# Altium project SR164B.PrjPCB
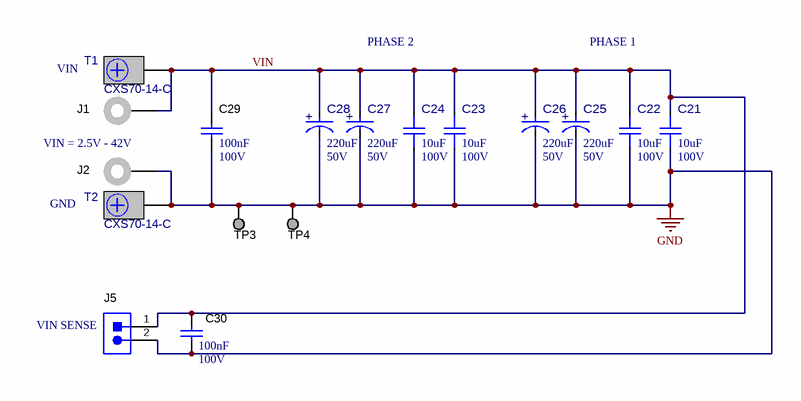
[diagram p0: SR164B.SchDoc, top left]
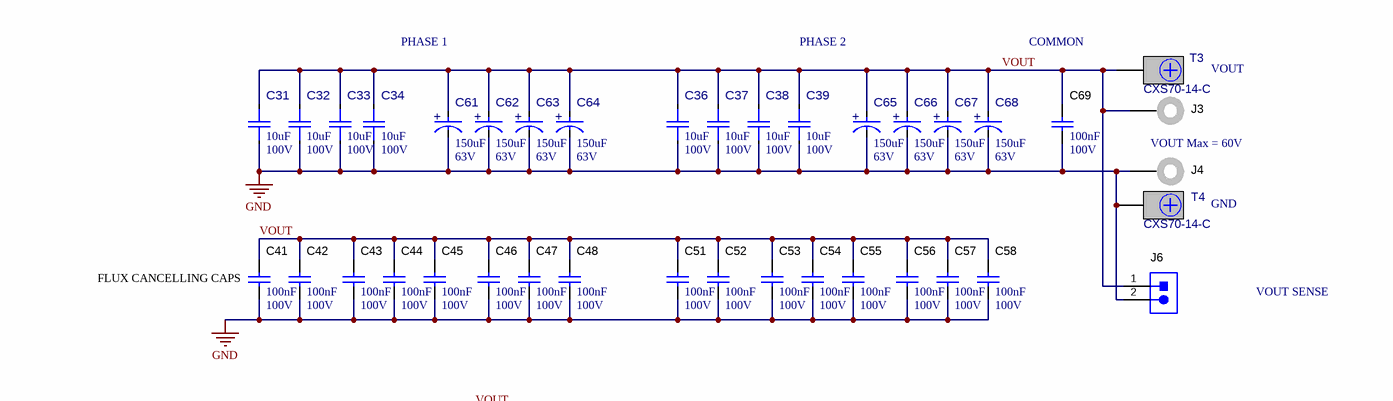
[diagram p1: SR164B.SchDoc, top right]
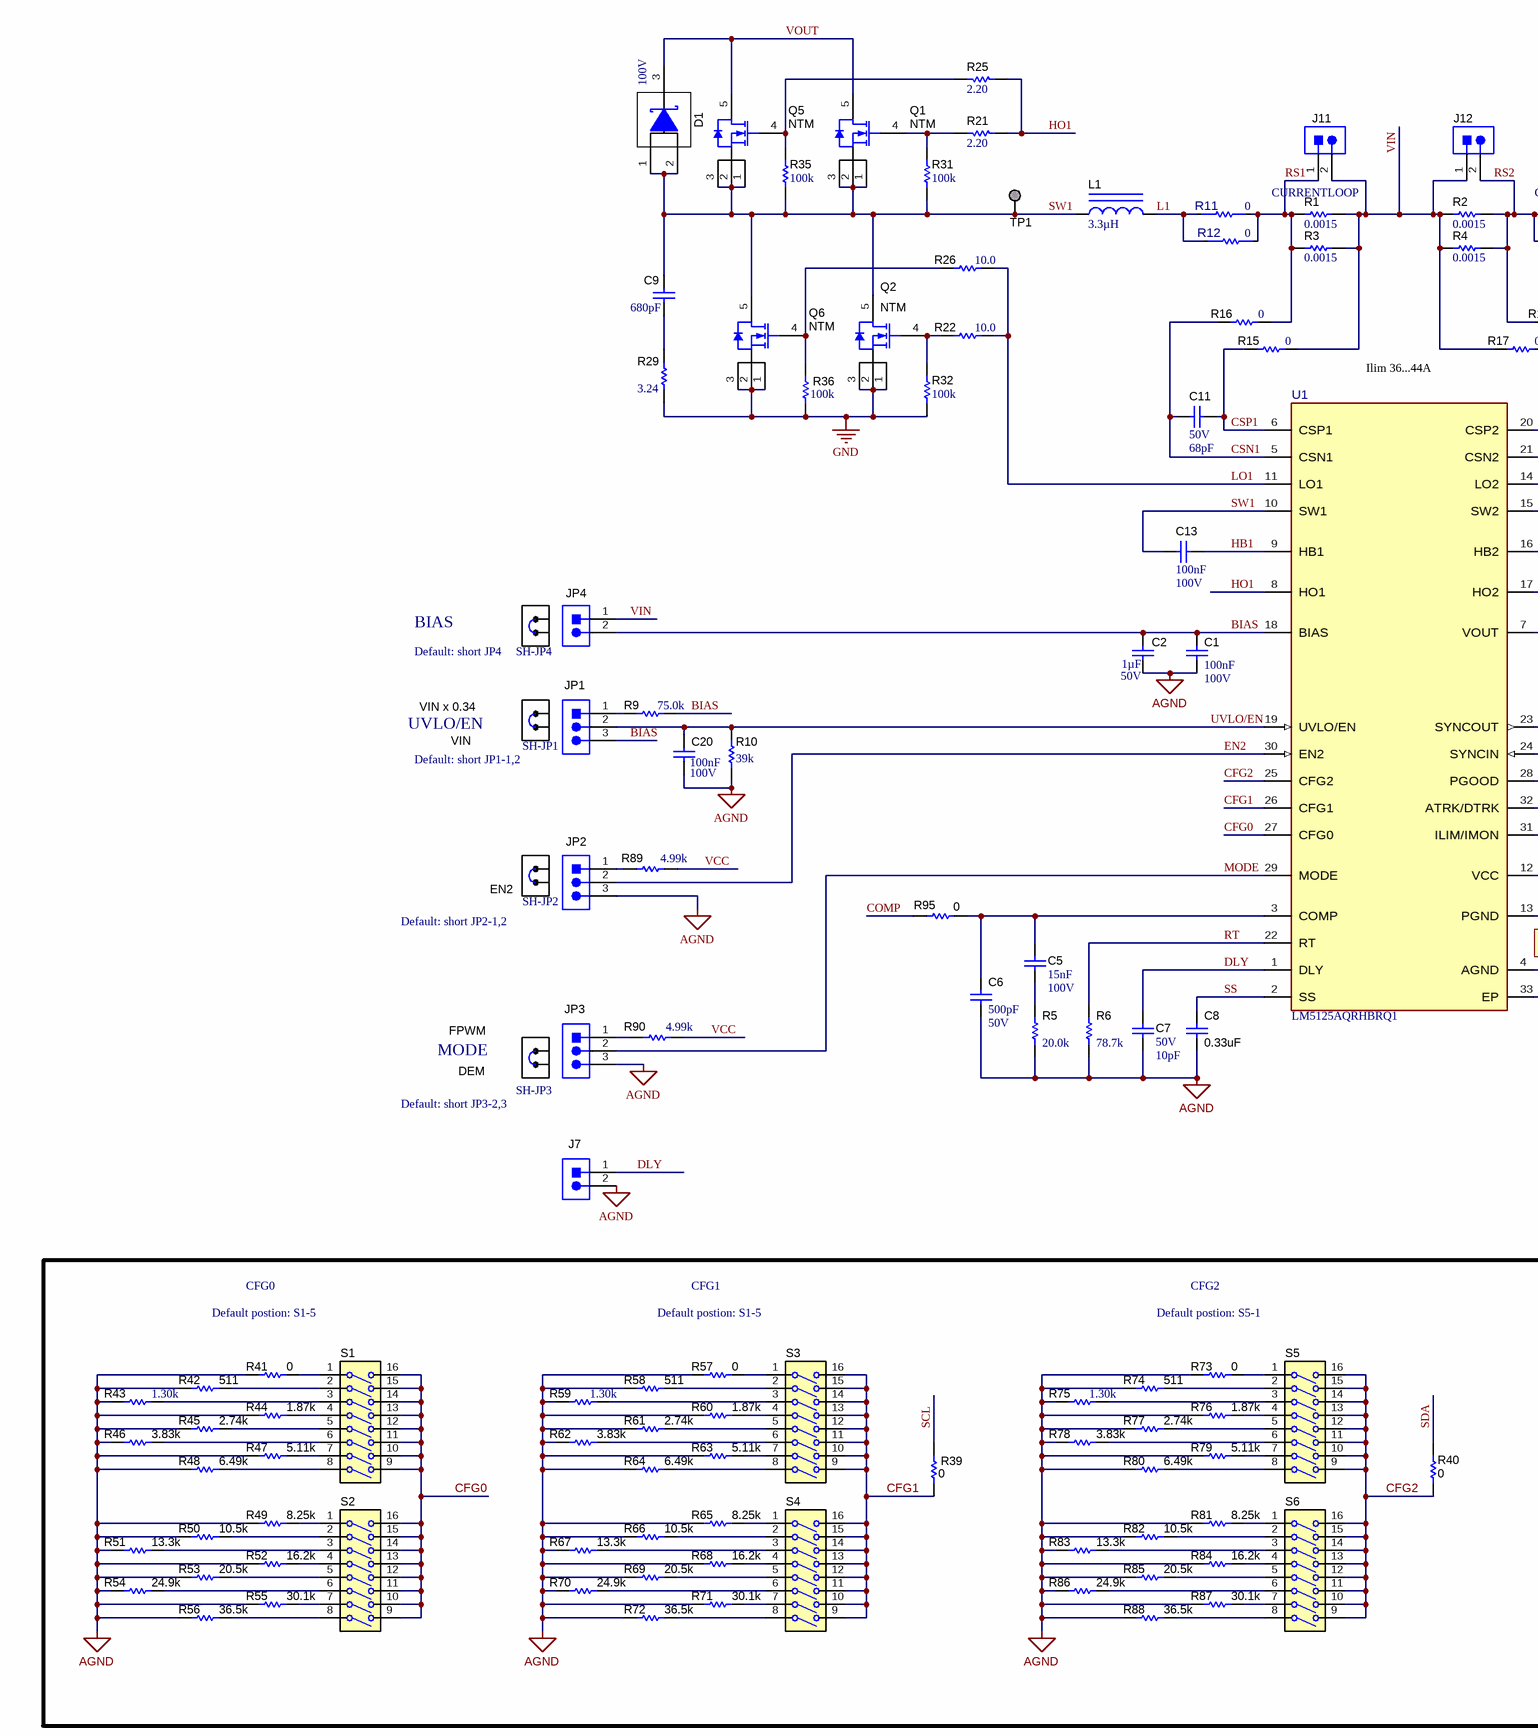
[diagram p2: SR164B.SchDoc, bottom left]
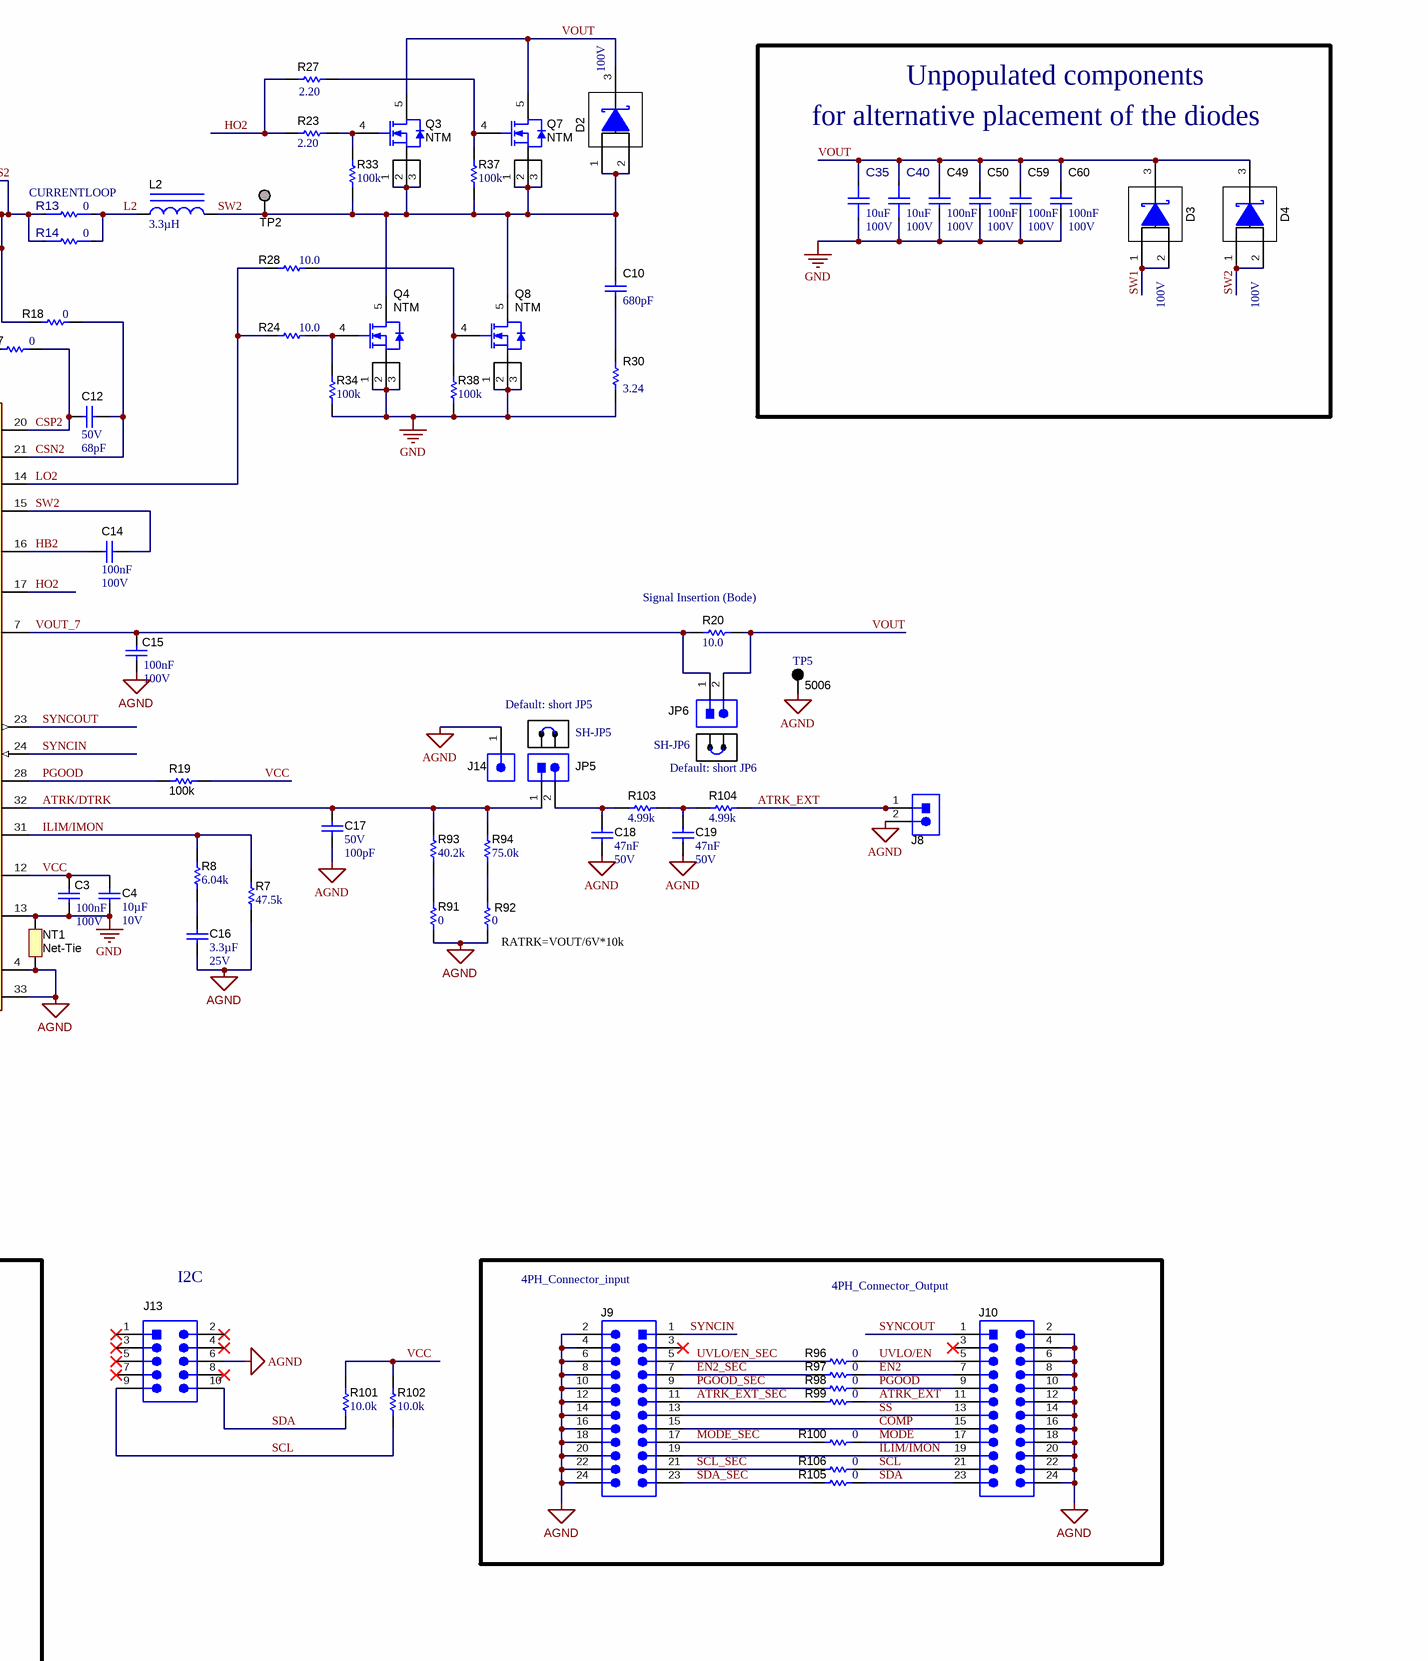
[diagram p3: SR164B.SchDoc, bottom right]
TID: N/A; SCH_Rev: B; PRJ_Title: LM5125AEVM-BST; PRJ_Number: SR164; PRJ_Customer: Public Release; PCB_Rev: A; CopyrightYear: 2025
2 sheets, 255 parts. Net scope: global (net labels, ports and power ports of the same name join across sheets).
Board file: SR164A.PcbDoc
Sheets:
  SR164B.SchDoc
  SR164B_Hardware.SchDoc

## Sheet SR164B.SchDoc: Schematc
size 558 x 431 mm; Date: Not shown in title block; ApprovedBy: Not shown in title block; CheckedBy: Not shown in title block; Author: Not shown in title block; CompanyName: Not shown in title block; Engineer: Not shown in title block; Organization: Not shown in title block; Address1: Not shown in title block; Address2: Not shown in title block; Address3: Not shown in title block; Address4: Not shown in title block; DocumentNumber: 1; Revision: Use project parameter SCH_Rev; SheetNumber: 1; SheetTotal: 2; PageSetup: Record=PageOptions¦CenterHorizontal=True¦CenterVertical=True¦PrintScale=1.00¦XCorrection=1.00¦YCorrection=1.00¦PrintKind=0¦BorderSize=5000000¦LeftOffset=0¦BottomOffset=0¦Orientation=2¦PaperLength=1000¦PaperWidth=1000¦Scale=100¦PaperSource=15¦PrintQuality=600¦MediaType=1¦DitherType=10¦PaperKind=Letter¦PrintScaleMode=1

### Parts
C1  Cap_F: 100nF  VDC_V: 100V  [0603S]  (hidden comment: GRM188R72A104KA35D)
C2  VDC_V: 50V  ValueDisplayed: 1µF  [0805L]  (hidden comment: GCM21BR71H105KA03K)
C3  Cap_F: 100nF  VDC_V: 100V  [0603S]  (hidden comment: GRM188R72A104KA35D)
C4  Cap_F: 10µF  VDC_V: 10V  [0805L]  (hidden comment: GCJ21BR71A106KE01L)
C5  Cap_F: 15nF  VDC_V: 100V  [0603S]  (hidden comment: GCM188R72A153KA37D)
C6  VDC_V: 50V  ValueDisplayed: 500pF  [0603S]  (hidden comment: CC0603JRNPO9BN501)
C7  VDC_V: 50V  ValueDisplayed: 10pF  [0603S]  (hidden comment: C1608C0G1H100D080AA)
C8  ValueDisplayed: 0.33uF  [0603S]  (hidden comment: C0603C334K8PACTU)
C9  value 680pF  [0603S]  (hidden comment: C0603C681K5RACTU)
C10  value 680pF  [0603S]  (hidden comment: C0603C681K5RACTU)
C11  VDC_V: 50V  ValueDisplayed: 68pF  [0402S]  (hidden comment: 04025A680FAT2A)
C12  VDC_V: 50V  ValueDisplayed: 68pF  [0402S]  (hidden comment: 04025A680FAT2A)
C13  Cap_F: 100nF  VDC_V: 100V  [0603S]  (hidden comment: GRM188R72A104KA35D)
C14  Cap_F: 100nF  VDC_V: 100V  [0603S]  (hidden comment: GRM188R72A104KA35D)
C15  Cap_F: 100nF  VDC_V: 100V  [0603S]  (hidden comment: GRM188R72A104KA35D)
C16  Cap_F: 3.3µF  VDC_V: 25V  [0805L]  (hidden comment: C2012X7R1E335K125AB)
C17  VDC_V: 50V  ValueDisplayed: 100pF  [0603S]  (hidden comment: C1608C0G1H101J080AE)
C18  Cap_F: 47nF  VDC_V: 50V  [0603S]  (hidden comment: C1608X7R1H473K080AA)
C19  Cap_F: 47nF  VDC_V: 50V  [0603S]  (hidden comment: C1608X7R1H473K080AA)
C20  Cap_F: 100nF  VDC_V: 100V  [0805L]  (hidden comment: CGA4J2X7R2A104K125AA)
C21  ValueDisplayed: 10uF  VDC_V: 100V  [FP-GRM32EC72A106KE05L_1210-MFG]  (hidden comment: GRM32EC72A106KE05L)
C22  ValueDisplayed: 10uF  VDC_V: 100V  [FP-GRM32EC72A106KE05L_1210-MFG]  (hidden comment: GRM32EC72A106KE05L)
C23  ValueDisplayed: 10uF  VDC_V: 100V  [FP-GRM32EC72A106KE05L_1210-MFG]  (hidden comment: GRM32EC72A106KE05L)
C24  ValueDisplayed: 10uF  VDC_V: 100V  [FP-GRM32EC72A106KE05L_1210-MFG]  (hidden comment: GRM32EC72A106KE05L)
C25  ValueDisplayed: 220uF  VDC_V: 50V  [FP-EEHZU1H221P_RADIAL_SMT-MFG]  (hidden comment: EEHZU1H221P)
C26  ValueDisplayed: 220uF  VDC_V: 50V  [FP-EEHZU1H221P_RADIAL_SMT-MFG]  (hidden comment: EEHZU1H221P)
C27  ValueDisplayed: 220uF  VDC_V: 50V  [FP-EEHZU1H221P_RADIAL_SMT-MFG]  (hidden comment: EEHZU1H221P)
C28  ValueDisplayed: 220uF  VDC_V: 50V  [FP-EEHZU1H221P_RADIAL_SMT-MFG]  (hidden comment: EEHZU1H221P)
C29  Cap_F: 100nF  VDC_V: 100V  [0603S]  (hidden comment: GRM188R72A104KA35D)
C30  Cap_F: 100nF  VDC_V: 100V  [0603S]  (hidden comment: GRM188R72A104KA35D)
C31  ValueDisplayed: 10uF  VDC_V: 100V  [FP-GRM32EC72A106KE05L_1210-MFG]  (hidden comment: GRM32EC72A106KE05L)
C32  ValueDisplayed: 10uF  VDC_V: 100V  [FP-GRM32EC72A106KE05L_1210-MFG]  (hidden comment: GRM32EC72A106KE05L)
C33  ValueDisplayed: 10uF  VDC_V: 100V  [FP-GRM32EC72A106KE05L_1210-MFG]  (hidden comment: GRM32EC72A106KE05L)
C34  ValueDisplayed: 10uF  VDC_V: 100V  [FP-GRM32EC72A106KE05L_1210-MFG]  (hidden comment: GRM32EC72A106KE05L)
C35  ValueDisplayed: 10uF  VDC_V: 100V  [FP-GRM32EC72A106KE05L_1210-MFG]  (hidden comment: GRM32EC72A106KE05L)
C36  ValueDisplayed: 10uF  VDC_V: 100V  [FP-GRM32EC72A106KE05L_1210-MFG]  (hidden comment: GRM32EC72A106KE05L)
C37  ValueDisplayed: 10uF  VDC_V: 100V  [FP-GRM32EC72A106KE05L_1210-MFG]  (hidden comment: GRM32EC72A106KE05L)
C38  ValueDisplayed: 10uF  VDC_V: 100V  [FP-GRM32EC72A106KE05L_1210-MFG]  (hidden comment: GRM32EC72A106KE05L)
C39  ValueDisplayed: 10uF  VDC_V: 100V  [FP-GRM32EC72A106KE05L_1210-MFG]  (hidden comment: GRM32EC72A106KE05L)
C40  ValueDisplayed: 10uF  VDC_V: 100V  [FP-GRM32EC72A106KE05L_1210-MFG]  (hidden comment: GRM32EC72A106KE05L)
C41  Cap_F: 100nF  VDC_V: 100V  [0603S]  (hidden comment: GRM188R72A104KA35D)
C42  Cap_F: 100nF  VDC_V: 100V  [0603S]  (hidden comment: GRM188R72A104KA35D)
C43  Cap_F: 100nF  VDC_V: 100V  [0603S]  (hidden comment: GRM188R72A104KA35D)
C44  Cap_F: 100nF  VDC_V: 100V  [0603S]  (hidden comment: GRM188R72A104KA35D)
C45  Cap_F: 100nF  VDC_V: 100V  [0603S]  (hidden comment: GRM188R72A104KA35D)
C46  Cap_F: 100nF  VDC_V: 100V  [0603S]  (hidden comment: GRM188R72A104KA35D)
C47  Cap_F: 100nF  VDC_V: 100V  [0603S]  (hidden comment: GRM188R72A104KA35D)
C48  Cap_F: 100nF  VDC_V: 100V  [0603S]  (hidden comment: GRM188R72A104KA35D)
C49  Cap_F: 100nF  VDC_V: 100V  [0603S]  (hidden comment: GRM188R72A104KA35D)
C50  Cap_F: 100nF  VDC_V: 100V  [0603S]  (hidden comment: GRM188R72A104KA35D)
C51  Cap_F: 100nF  VDC_V: 100V  [0603S]  (hidden comment: GRM188R72A104KA35D)
C52  Cap_F: 100nF  VDC_V: 100V  [0603S]  (hidden comment: GRM188R72A104KA35D)
C53  Cap_F: 100nF  VDC_V: 100V  [0603S]  (hidden comment: GRM188R72A104KA35D)
C54  Cap_F: 100nF  VDC_V: 100V  [0603S]  (hidden comment: GRM188R72A104KA35D)
C55  Cap_F: 100nF  VDC_V: 100V  [0603S]  (hidden comment: GRM188R72A104KA35D)
C56  Cap_F: 100nF  VDC_V: 100V  [0603S]  (hidden comment: GRM188R72A104KA35D)
C57  Cap_F: 100nF  VDC_V: 100V  [0603S]  (hidden comment: GRM188R72A104KA35D)
C58  Cap_F: 100nF  VDC_V: 100V  [0603S]  (hidden comment: GRM188R72A104KA35D)
C59  Cap_F: 100nF  VDC_V: 100V  [0603S]  (hidden comment: GRM188R72A104KA35D)
C60  Cap_F: 100nF  VDC_V: 100V  [0603S]  (hidden comment: GRM188R72A104KA35D)
C61  ValueDisplayed: 150uF  VDC_V: 63V  [FP-EEHZU1J151P_RADIAL_SMT-MFG]  (hidden comment: EEHZU1J151P)
C62  ValueDisplayed: 150uF  VDC_V: 63V  [FP-EEHZU1J151P_RADIAL_SMT-MFG]  (hidden comment: EEHZU1J151P)
C63  ValueDisplayed: 150uF  VDC_V: 63V  [FP-EEHZU1J151P_RADIAL_SMT-MFG]  (hidden comment: EEHZU1J151P)
C64  ValueDisplayed: 150uF  VDC_V: 63V  [FP-EEHZU1J151P_RADIAL_SMT-MFG]  (hidden comment: EEHZU1J151P)
C65  ValueDisplayed: 150uF  VDC_V: 63V  [FP-EEHZU1J151P_RADIAL_SMT-MFG]  (hidden comment: EEHZU1J151P)
C66  ValueDisplayed: 150uF  VDC_V: 63V  [FP-EEHZU1J151P_RADIAL_SMT-MFG]  (hidden comment: EEHZU1J151P)
C67  ValueDisplayed: 150uF  VDC_V: 63V  [FP-EEHZU1J151P_RADIAL_SMT-MFG]  (hidden comment: EEHZU1J151P)
C68  ValueDisplayed: 150uF  VDC_V: 63V  [FP-EEHZU1J151P_RADIAL_SMT-MFG]  (hidden comment: EEHZU1J151P)
C69  Cap_F: 100nF  VDC_V: 100V  [0603S]  (hidden comment: GRM188R72A104KA35D)
D1  value 100V  [TO-277A]  (hidden comment: V12P10-M3/86A)
D2  value 100V  [TO-277A]  (hidden comment: V12P10-M3/86A)
D3  value 100V  [TO-277A]  (hidden comment: V12P10-M3/86A)
D4  value 100V  [TO-277A]  (hidden comment: V12P10-M3/86A)
J1  108-0740-001  [Johnson_108-0740-001]  (value not drawn)
J2  108-0740-001  [Johnson_108-0740-001]  (value not drawn)
J3  108-0740-001  [Johnson_108-0740-001]  (value not drawn)
J4  108-0740-001  [Johnson_108-0740-001]  (value not drawn)
J5  61300211121  [WURTH_61300211121]  (value not drawn)
J6  61300211121  [WURTH_61300211121]  (value not drawn)
J7  61300211121  [WURTH_61300211121]  (value not drawn)
J8  61300211121  [WURTH_61300211121]  (value not drawn)
J9  TSW-112-07-G-D  [TSW-112-07-G-D]  (value not drawn)
J10  TSW-112-07-G-D  [TSW-112-07-G-D]  (value not drawn)
J11  61300211121  [WURTH_61300211121]  (value not drawn)
J12  61300211121  [WURTH_61300211121]  (value not drawn)
J13  Header_5x2  [CONN_2510-6002]  (value not drawn)
J14  61300111121  [WURTH_61300111121]  (value not drawn)
JP1  61300311121  [WURTH_61300311121]  (value not drawn)
JP2  61300311121  [WURTH_61300311121]  (value not drawn)
JP3  61300311121  [WURTH_61300311121]  (value not drawn)
JP4  61300211121  [WURTH_61300211121]  (value not drawn)
JP5  61300211121  [WURTH_61300211121]  (value not drawn)
JP6  61300211121  [WURTH_61300211121]  (value not drawn)
L1  ValueDisplayed: 3.3µH  [IHLP-6767GZ]  (hidden comment: IHLP6767GZER3R3M5A)
L2  ValueDisplayed: 3.3µH  [IHLP-6767GZ]  (hidden comment: IHLP6767GZER3R3M5A)
NT1  Net-Tie  [Net-Tie_10milWide_30milLong]  (net tie, no BOM)
Q1  NTM  [SO-8FL]
Q2  NTM  [SO-8FL]
Q3  NTM  [SO-8FL]
Q4  NTM  [SO-8FL]
Q5  NTM  [SO-8FL]
Q6  NTM  [SO-8FL]
Q7  NTM  [SO-8FL]
Q8  NTM  [SO-8FL]
R1  ValueDisplayed: 0.0015  [2512_WIDE]  (hidden comment: PML100HZPJV1L5)
R2  ValueDisplayed: 0.0015  [2512_WIDE]  (hidden comment: PML100HZPJV1L5)
R3  ValueDisplayed: 0.0015  [2512_WIDE]  (hidden comment: PML100HZPJV1L5)
R4  ValueDisplayed: 0.0015  [2512_WIDE]  (hidden comment: PML100HZPJV1L5)
R5  ValueDisplayed: 20.0k  [0603S]  (hidden comment: CRCW060320K0FKEA)
R6  ValueDisplayed: 78.7k  [0603S]  (hidden comment: RT0603BRD0778K7L)
R7  ValueDisplayed: 47.5k  [0603S]  (hidden comment: RT0603BRD0747K5L)
R8  ValueDisplayed: 6.04k  [0603S]  (hidden comment: CRCW06036K04FKEA)
R9  ValueDisplayed: 75.0k  [0805L]  (hidden comment: CRCW080575K0FKEA)
R10  ValueDisplayed: 39k  [0805L]  (hidden comment: CRCW080539K0JNEA)
R11  value 0  [FP-WSL080500000ZEA9_0805-MFG]  (hidden comment: WSL080500000ZEA9)
R12  value 0  [FP-WSL080500000ZEA9_0805-MFG]  (hidden comment: WSL080500000ZEA9)
R13  value 0  [FP-WSL080500000ZEA9_0805-MFG]  (hidden comment: WSL080500000ZEA9)
R14  value 0  [FP-WSL080500000ZEA9_0805-MFG]  (hidden comment: WSL080500000ZEA9)
R15  ValueDisplayed: 0  [0603S]  (hidden comment: RMCF0603ZT0R00)
R16  ValueDisplayed: 0  [0603S]  (hidden comment: RMCF0603ZT0R00)
R17  ValueDisplayed: 0  [0603S]  (hidden comment: RMCF0603ZT0R00)
R18  ValueDisplayed: 0  [0603S]  (hidden comment: RMCF0603ZT0R00)
R19  ValueDisplayed: 100k  [0603S]  (hidden comment: CRCW0603100KFKEA)
R20  ValueDisplayed: 10.0  [0603S]  (hidden comment: CRCW060310R0FKEA)
R21  ValueDisplayed: 2.20  [0603S]  (hidden comment: ERJ-3RQF2R2V)
R22  ValueDisplayed: 10.0  [0603S]  (hidden comment: CRCW060310R0FKEA)
R23  ValueDisplayed: 2.20  [0603S]  (hidden comment: ERJ-3RQF2R2V)
R24  ValueDisplayed: 10.0  [0603S]  (hidden comment: CRCW060310R0FKEA)
R25  ValueDisplayed: 2.20  [0603S]  (hidden comment: ERJ-3RQF2R2V)
R26  ValueDisplayed: 10.0  [0603S]  (hidden comment: CRCW060310R0FKEA)
R27  ValueDisplayed: 2.20  [0603S]  (hidden comment: ERJ-3RQF2R2V)
R28  ValueDisplayed: 10.0  [0603S]  (hidden comment: CRCW060310R0FKEA)
R29  ValueDisplayed: 3.24  [1206L]  (hidden comment: CRCW12063R24FKEA)
R30  ValueDisplayed: 3.24  [1206L]  (hidden comment: CRCW12063R24FKEA)
R31  ValueDisplayed: 100k  [0402S]  (hidden comment: CRCW0402100KFKED)
R32  ValueDisplayed: 100k  [0402S]  (hidden comment: CRCW0402100KFKED)
R33  ValueDisplayed: 100k  [0402S]  (hidden comment: CRCW0402100KFKED)
R34  ValueDisplayed: 100k  [0402S]  (hidden comment: CRCW0402100KFKED)
R35  ValueDisplayed: 100k  [0402S]  (hidden comment: CRCW0402100KFKED)
R36  ValueDisplayed: 100k  [0402S]  (hidden comment: CRCW0402100KFKED)
R37  ValueDisplayed: 100k  [0402S]  (hidden comment: CRCW0402100KFKED)
R38  ValueDisplayed: 100k  [0402S]  (hidden comment: CRCW0402100KFKED)
R39  ValueDisplayed: 0  [0603S]  (hidden comment: RMCF0603ZT0R00)
R40  ValueDisplayed: 0  [0603S]  (hidden comment: RMCF0603ZT0R00)
R41  ValueDisplayed: 0  [0603S]  (hidden comment: RMCF0603ZT0R00)
R42  ValueDisplayed: 511  [0603S]  (hidden comment: CRCW0603511RFKEA)
R43  ValueDisplayed: 1.30k  [0603S]  (hidden comment: CRCW06031K30FKEA)
R44  ValueDisplayed: 1.87k  [0603S]  (hidden comment: CRCW06031K87FKEA)
R45  ValueDisplayed: 2.74k  [0603S]  (hidden comment: CRCW06032K74FKEA)
R46  ValueDisplayed: 3.83k  [0603S]  (hidden comment: CRCW06033K83FKEA)
R47  ValueDisplayed: 5.11k  [0603S]  (hidden comment: CRCW06035K11FKEA)
R48  ValueDisplayed: 6.49k  [0603S]  (hidden comment: CRCW06036K49FKEA)
R49  ValueDisplayed: 8.25k  [0603S]  (hidden comment: CRCW06038K25FKEA)
R50  ValueDisplayed: 10.5k  [0603S]  (hidden comment: CRCW060310K5FKEA)
R51  ValueDisplayed: 13.3k  [0603S]  (hidden comment: CRCW060313K3FKEA)
R52  ValueDisplayed: 16.2k  [0603S]  (hidden comment: CRCW060316K2FKEA)
R53  ValueDisplayed: 20.5k  [0603S]  (hidden comment: CRCW060320K5FKEA)
R54  ValueDisplayed: 24.9k  [0603S]  (hidden comment: CRCW060324K9FKEA)
R55  ValueDisplayed: 30.1k  [0603S]  (hidden comment: CRCW060330K1FKEA)
R56  ValueDisplayed: 36.5k  [0603S]  (hidden comment: CRCW060336K5FKEA)
R57  ValueDisplayed: 0  [0603S]  (hidden comment: RMCF0603ZT0R00)
R58  ValueDisplayed: 511  [0603S]  (hidden comment: CRCW0603511RFKEA)
R59  ValueDisplayed: 1.30k  [0603S]  (hidden comment: CRCW06031K30FKEA)
R60  ValueDisplayed: 1.87k  [0603S]  (hidden comment: CRCW06031K87FKEA)
R61  ValueDisplayed: 2.74k  [0603S]  (hidden comment: CRCW06032K74FKEA)
R62  ValueDisplayed: 3.83k  [0603S]  (hidden comment: CRCW06033K83FKEA)
R63  ValueDisplayed: 5.11k  [0603S]  (hidden comment: CRCW06035K11FKEA)
R64  ValueDisplayed: 6.49k  [0603S]  (hidden comment: CRCW06036K49FKEA)
R65  ValueDisplayed: 8.25k  [0603S]  (hidden comment: CRCW06038K25FKEA)
R66  ValueDisplayed: 10.5k  [0603S]  (hidden comment: CRCW060310K5FKEA)
R67  ValueDisplayed: 13.3k  [0603S]  (hidden comment: CRCW060313K3FKEA)
R68  ValueDisplayed: 16.2k  [0603S]  (hidden comment: CRCW060316K2FKEA)
R69  ValueDisplayed: 20.5k  [0603S]  (hidden comment: CRCW060320K5FKEA)
R70  ValueDisplayed: 24.9k  [0603S]  (hidden comment: CRCW060324K9FKEA)
R71  ValueDisplayed: 30.1k  [0603S]  (hidden comment: CRCW060330K1FKEA)
R72  ValueDisplayed: 36.5k  [0603S]  (hidden comment: CRCW060336K5FKEA)
R73  ValueDisplayed: 0  [0603S]  (hidden comment: RMCF0603ZT0R00)
R74  ValueDisplayed: 511  [0603S]  (hidden comment: CRCW0603511RFKEA)
R75  ValueDisplayed: 1.30k  [0603S]  (hidden comment: CRCW06031K30FKEA)
R76  ValueDisplayed: 1.87k  [0603S]  (hidden comment: CRCW06031K87FKEA)
R77  ValueDisplayed: 2.74k  [0603S]  (hidden comment: CRCW06032K74FKEA)
R78  ValueDisplayed: 3.83k  [0603S]  (hidden comment: CRCW06033K83FKEA)
R79  ValueDisplayed: 5.11k  [0603S]  (hidden comment: CRCW06035K11FKEA)
R80  ValueDisplayed: 6.49k  [0603S]  (hidden comment: CRCW06036K49FKEA)
R81  ValueDisplayed: 8.25k  [0603S]  (hidden comment: CRCW06038K25FKEA)
R82  ValueDisplayed: 10.5k  [0603S]  (hidden comment: CRCW060310K5FKEA)
R83  ValueDisplayed: 13.3k  [0603S]  (hidden comment: CRCW060313K3FKEA)
R84  ValueDisplayed: 16.2k  [0603S]  (hidden comment: CRCW060316K2FKEA)
R85  ValueDisplayed: 20.5k  [0603S]  (hidden comment: CRCW060320K5FKEA)
R86  ValueDisplayed: 24.9k  [0603S]  (hidden comment: CRCW060324K9FKEA)
R87  ValueDisplayed: 30.1k  [0603S]  (hidden comment: CRCW060330K1FKEA)
R88  ValueDisplayed: 36.5k  [0603S]  (hidden comment: CRCW060336K5FKEA)
R89  ValueDisplayed: 4.99k  [0603S]  (hidden comment: CRCW06034K99FKEA)
R90  ValueDisplayed: 4.99k  [0603S]  (hidden comment: CRCW06034K99FKEA)
R91  ValueDisplayed: 0  [0805L]  (hidden comment: CRCW08050000Z0EA)
R92  ValueDisplayed: 0  [0805L]  (hidden comment: CRCW08050000Z0EA)
R93  ValueDisplayed: 40.2k  [0805L]  (hidden comment: CRCW080540K2FKEA)
R94  ValueDisplayed: 75.0k  [0805L]  (hidden comment: CRCW080575K0FKEA)
R95  ValueDisplayed: 0  [0603S]  (hidden comment: ERJ-3GEY0R00V)
R96  ValueDisplayed: 0  [0805L]  (hidden comment: CRCW08050000Z0EA)
R97  ValueDisplayed: 0  [0805L]  (hidden comment: CRCW08050000Z0EA)
R98  ValueDisplayed: 0  [0805L]  (hidden comment: CRCW08050000Z0EA)
R99  ValueDisplayed: 0  [0805L]  (hidden comment: CRCW08050000Z0EA)
R100  ValueDisplayed: 0  [0805L]  (hidden comment: CRCW08050000Z0EA)
R101  ValueDisplayed: 10.0k  [0805L]  (hidden comment: CRCW080510K0FKEA)
R102  ValueDisplayed: 10.0k  [0805L]  (hidden comment: CRCW080510K0FKEA)
R103  ValueDisplayed: 4.99k  [0603S]  (hidden comment: CRCW06034K99FKEA)
R104  ValueDisplayed: 4.99k  [0603S]  (hidden comment: CRCW06034K99FKEA)
R105  ValueDisplayed: 0  [0805L]  (hidden comment: CRCW08050000Z0EA)
R106  ValueDisplayed: 0  [0805L]  (hidden comment: CRCW08050000Z0EA)
S1  218-8LPST  [SW_218-8LP]  (value not drawn)
S2  218-8LPST  [SW_218-8LP]  (value not drawn)
S3  218-8LPST  [SW_218-8LP]  (value not drawn)
S4  218-8LPST  [SW_218-8LP]  (value not drawn)
S5  218-8LPST  [SW_218-8LP]  (value not drawn)
S6  218-8LPST  [SW_218-8LP]  (value not drawn)
SH-JP1  SPC02SYAN  [SPC02SYAN]  (value not drawn)
SH-JP2  SPC02SYAN  [SPC02SYAN]  (value not drawn)
SH-JP3  SPC02SYAN  [SPC02SYAN]  (value not drawn)
SH-JP4  SPC02SYAN  [SPC02SYAN]  (value not drawn)
SH-JP5  SPC02SYAN  [SPC02SYAN]  (value not drawn)
SH-JP6  SPC02SYAN  [SPC02SYAN]  (value not drawn)
T1  CXS70-14-C  [Panduit_CXS70-14-C]
T2  CXS70-14-C  [Panduit_CXS70-14-C]
T3  CXS70-14-C  [Panduit_CXS70-14-C]
T4  CXS70-14-C  [Panduit_CXS70-14-C]
TP1  RCU-0C  [TE_RCU]  (value not drawn)
TP2  RCU-0C  [TE_RCU]  (value not drawn)
TP3  RCU-0C  [TE_RCU]  (value not drawn)
TP4  RCU-0C  [TE_RCU]  (value not drawn)
TP5  5006  [Keystone5006]
U1  LM5125AQRHBRQ1  [RHB0032U-MFG]

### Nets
AGND: C1.2 C2.1 C6.2 C7.2 C8.2 C15.2 C16.2 C17.2 C18.2 C19.2 C20.2 J7.2 J8.2 J9.2 J9.4 J9.6 J9.8 J9.10 J9.12 J9.14 J9.16 J9.18 J9.20 J9.22 J9.24 J10.2 J10.4 J10.6 J10.8 J10.10 J10.12 J10.14 J10.16 J10.18 J10.20 J10.22 J10.24 J13.6 J14.1 JP2.3 JP3.3 NT1.1 R5.1 R6.1 R7.1 R10.2 R41.2 R42.1 R43.2 R44.1 R45.2 R46.1 R47.1 R48.1 R49.1 R50.1 R51.1 R52.2 R53.1 R54.1 R55.1 R56.2 R57.2 R58.1 R59.2 R60.1 R61.2 R62.1 R63.1 R64.1 R65.1 R66.1 R67.1 R68.2 R69.1 R70.1 R71.1 R72.2 R73.2 R74.1 R75.2 R76.1 R77.2 R78.1 R79.1 R80.1 R81.1 R82.1 R83.1 R84.2 R85.1 R86.1 R87.1 R88.2 R91.1 R92.1 TP5.1 U1.4(AGND) U1.33(EP)
GND: C3.2 C4.2 C21.1 C22.1 C23.1 C24.1 C25.1(CATHODE) C26.1(CATHODE) C27.1(CATHODE) C28.1(CATHODE) C29.2 C30.2 C31.1 C32.1 C33.1 C34.1 C35.1 C36.1 C37.1 C38.1 C39.1 C40.1 C41.2 C42.2 C43.2 C44.2 C45.2 C46.2 C47.2 C48.2 C49.2 C50.2 C51.2 C52.2 C53.2 C54.2 C55.2 C56.2 C57.2 C58.2 C59.2 C60.2 C61.1(CATHODE) C62.1(CATHODE) C63.1(CATHODE) C64.1(CATHODE) C65.1(CATHODE) C66.1(CATHODE) C67.1(CATHODE) C68.1(CATHODE) C69.2 J2.1 J4.1 J5.2 J6.2 NT1.2 Q2.1(S) Q2.2(S) Q2.3(S) Q4.1(S) Q4.2(S) Q4.3(S) Q6.1(S) Q6.2(S) Q6.3(S) Q8.1(S) Q8.2(S) Q8.3(S) R29.1 R30.1 R32.1 R34.1 R36.1 R38.1 T2.1 T4.1 TP3.1 TP4.1 U1.13(PGND)
ATRK/DTRK: C17.1 JP5.1 R93.2 R94.2 U1.32(ATRK/DTRK)
ATRK_EXT: J8.1 J10.11 R99.1 R104.2
ATRK_EXT_SEC: J9.11 R99.2
BIAS: C1.1 C2.2 JP1.3 JP4.2 R9.1 U1.18(BIAS)
CFG0: S1.9(8A) S1.10(7A) S1.11(6A) S1.12(5A) S1.13(4A) S1.14(3A) S1.15(2A) S1.16(1A) S2.9(8A) S2.10(7A) S2.11(6A) S2.12(5A) S2.13(4A) S2.14(3A) S2.15(2A) S2.16(1A) U1.27(CFG0)
CFG1: R39.2 S3.9(8A) S3.10(7A) S3.11(6A) S3.12(5A) S3.13(4A) S3.14(3A) S3.15(2A) S3.16(1A) S4.9(8A) S4.10(7A) S4.11(6A) S4.12(5A) S4.13(4A) S4.14(3A) S4.15(2A) S4.16(1A) U1.26(CFG1)
CFG2: R40.2 S5.9(8A) S5.10(7A) S5.11(6A) S5.12(5A) S5.13(4A) S5.14(3A) S5.15(2A) S5.16(1A) S6.9(8A) S6.10(7A) S6.11(6A) S6.12(5A) S6.13(4A) S6.14(3A) S6.15(2A) S6.16(1A) U1.25(CFG2)
COMP: J9.15 J10.15 R95.1
CSN1: C11.2 R16.1 U1.5(CSN1)
CSN2: C12.1 R18.1 U1.21(CSN2)
CSP1: C11.1 R15.1 U1.6(CSP1)
CSP2: C12.2 R17.1 U1.20(CSP2)
DLY: C7.1 J7.1 U1.1(DLY)
EN2: J10.7 JP2.2 R97.1 U1.30(EN2)
EN2_SEC: J9.7 R97.2
HB1: C13.2 U1.9(HB1)
HB2: C14.1 U1.16(HB2)
HO1: R21.2 R25.2 U1.8(HO1)
HO2: R23.1 R27.1 U1.17(HO2)
ILIM/IMON: J9.19 J10.19 R7.2 R8.2 U1.31(ILIM/IMON)
L1: L1.2 R11.1 R12.1
L2: L2.1 R13.2 R14.2
LO1: R22.1 R26.1 U1.11(LO1)
LO2: R24.2 R28.2 U1.14(LO2)
MODE: J10.17 JP3.2 R100.1 U1.29(MODE)
MODE_SEC: J9.17 R100.2
PGOOD: J10.9 R19.2 R98.1 U1.28(PGOOD)
PGOOD_SEC: J9.9 R98.2
RS1: J11.1 R1.1 R3.1 R11.2 R12.2 R16.2
RS2: J12.2 R2.2 R4.2 R13.1 R14.1 R18.2
RT: R6.2 U1.22(RT)
SCL: J10.21 J13.9 R39.1 R102.1 R106.1
SCL_SEC: J9.21 R106.2
SDA: J10.23 J13.10 R40.1 R101.1 R105.1
SDA_SEC: J9.23 R105.2
SS: C8.1 J9.13 J10.13 U1.2(SS)
SW1: C9.1 C13.1 D1.1(A) D1.2(A) D3.1(A) D3.2(A) L1.1 Q1.1(S) Q1.2(S) Q1.3(S) Q2.5(D) Q5.1(S) Q5.2(S) Q5.3(S) Q6.5(D) R31.1 R35.1 TP1.1 U1.10(SW1)
SW2: C10.1 C14.2 D2.1(A) D2.2(A) D4.1(A) D4.2(A) L2.2 Q3.1(S) Q3.2(S) Q3.3(S) Q4.5(D) Q7.1(S) Q7.2(S) Q7.3(S) Q8.5(D) R33.1 R37.1 TP2.1 U1.15(SW2)
SYNCIN: J9.1 U1.24(SYNCIN)
SYNCOUT: J10.1 U1.23(SYNCOUT)
UVLO/EN: C20.1 J10.5 JP1.2 R10.1 R96.1 U1.19(UVLO/EN)
UVLO/EN_SEC: J9.5 R96.2
VCC: C3.1 C4.1 R19.1 R89.2 R90.2 R101.2 R102.2 U1.12(VCC)
VIN: C21.2 C22.2 C23.2 C24.2 C25.2(ANODE) C26.2(ANODE) C27.2(ANODE) C28.2(ANODE) C29.1 C30.1 J1.1 J5.1 J11.2 J12.1 JP4.1 R1.2 R2.1 R3.2 R4.1 R15.2 R17.2 T1.1
VOUT: C31.2 C32.2 C33.2 C34.2 C35.2 C36.2 C37.2 C38.2 C39.2 C40.2 C41.1 C42.1 C43.1 C44.1 C45.1 C46.1 C47.1 C48.1 C49.1 C50.1 C51.1 C52.1 C53.1 C54.1 C55.1 C56.1 C57.1 C58.1 C59.1 C60.1 C61.2(ANODE) C62.2(ANODE) C63.2(ANODE) C64.2(ANODE) C65.2(ANODE) C66.2(ANODE) C67.2(ANODE) C68.2(ANODE) C69.1 D1.3(K) D2.3(K) D3.3(K) D4.3(K) J3.1 J6.1 JP6.2 Q1.5(D) Q3.5(D) Q5.5(D) Q7.5(D) R20.1 T3.1
VOUT_7: C15.1 JP6.1 R20.2 U1.7(VOUT)
NetC5_1: C5.1 C6.1 R95.2 U1.3(COMP)
NetC5_2: C5.2 R5.2
NetC9_2: C9.2 R29.2
NetC10_2: C10.2 R30.2
NetC16_1: C16.1 R8.1
NetC18_1: C18.1 JP5.2 R103.1
NetC19_1: C19.1 R103.2 R104.1
NetJP1_1: JP1.1 R9.2
NetJP2_1: JP2.1 R89.1
NetJP3_1: JP3.1 R90.1
NetQ1_4: Q1.4(G) R21.1 R31.2
NetQ2_4: Q2.4(G) R22.2 R32.2
NetQ3_4: Q3.4(G) R23.2 R33.2
NetQ4_4: Q4.4(G) R24.1 R34.2
NetQ5_4: Q5.4(G) R25.1 R35.2
NetQ6_4: Q6.4(G) R26.2 R36.2
NetQ7_4: Q7.4(G) R27.2 R37.2
NetQ8_4: Q8.4(G) R28.1 R38.2
NetR41_1: R41.1 S1.1
NetR42_2: R42.2 S1.2
NetR43_1: R43.1 S1.3
NetR44_2: R44.2 S1.4
NetR45_1: R45.1 S1.5
NetR46_2: R46.2 S1.6
NetR47_2: R47.2 S1.7
NetR48_2: R48.2 S1.8
NetR49_2: R49.2 S2.1
NetR50_2: R50.2 S2.2
NetR51_2: R51.2 S2.3
NetR52_1: R52.1 S2.4
NetR53_2: R53.2 S2.5
NetR54_2: R54.2 S2.6
NetR55_2: R55.2 S2.7
NetR56_1: R56.1 S2.8
NetR57_1: R57.1 S3.1
NetR58_2: R58.2 S3.2
NetR59_1: R59.1 S3.3
NetR60_2: R60.2 S3.4
NetR61_1: R61.1 S3.5
NetR62_2: R62.2 S3.6
NetR63_2: R63.2 S3.7
NetR64_2: R64.2 S3.8
NetR65_2: R65.2 S4.1
NetR66_2: R66.2 S4.2
NetR67_2: R67.2 S4.3
NetR68_1: R68.1 S4.4
NetR69_2: R69.2 S4.5
NetR70_2: R70.2 S4.6
NetR71_2: R71.2 S4.7
NetR72_1: R72.1 S4.8
NetR73_1: R73.1 S5.1
NetR74_2: R74.2 S5.2
NetR75_1: R75.1 S5.3
NetR76_2: R76.2 S5.4
NetR77_1: R77.1 S5.5
NetR78_2: R78.2 S5.6
NetR79_2: R79.2 S5.7
NetR80_2: R80.2 S5.8
NetR81_2: R81.2 S6.1
NetR82_2: R82.2 S6.2
NetR83_2: R83.2 S6.3
NetR84_1: R84.1 S6.4
NetR85_2: R85.2 S6.5
NetR86_2: R86.2 S6.6
NetR87_2: R87.2 S6.7
NetR88_1: R88.1 S6.8
NetR91_2: R91.2 R93.1
NetR92_2: R92.2 R94.1

Not connected (* = marked no-connect by the designer): J9 3*; J10 3*; J13 1* 2* 3* 4* 5* 7* 8*

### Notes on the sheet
- VIN
- PHASE 2
- PHASE 1
- COMMON
- VOUT
- VIN = 2.5V - 42V
- VOUT Max = 60V
- GND
- (near C41) FLUX CANCELLING CAPS
- (near J5) VIN SENSE
- (near J6) VOUT SENSE
- Unpopulated components
- for alternative placement of the diodes
- (near R11) CURRENTLOOP
- (near R13) CURRENTLOOP
- Ilim 36...44A
- BIAS
- (near SH-JP4) Default: short JP4
- (near R20) Signal Insertion (Bode)
- UVLO/EN
- VIN x 0.34
- (near SH-JP5) Default: short JP5
- Default: short JP1-1,2
- (near SH-JP6) Default: short JP6
- Default: short JP2-1,2
- (near SH-JP2) EN2
- (near R92) RATRK=VOUT/6V*10k
- MODE
- FPWM
- Default: short JP3-2,3
- DEM
- Default postion: S1-5
- CFG0
- CFG1
- Default postion: S5-1
- CFG2
- (near J13) I2C
- (near J9) 4PH_Connector_input
- 4PH_Connector_Output

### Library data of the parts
C1 C3 C13-C15 C29 C30 C41-C60 C69 = CMP-0007469-4: CAP, CERM, 0.1 uF, 100 V, +/- 10%, X7R, 0603; Manufacturer: MuRata; TaMin_C: -55°C; Polarized: N; SizeAreaWB_mm2: 4.68; Value1: Unknown; U/M: EA; Value: 0.1uF; TaMax_C: 125°C; SizeZ_mm: 1; SizeX_mm: 1.6; SizeY_mm: 0.8; Cap_Case: 0603; SizeArea_mm2: 1.28; AEC Category: Q200
C2 = CMP-0086249-1: CAP, CERM, 1 µF, 50 V,+/- 10%, X7R, AEC-Q200 Grade 1, 0805; Manufacturer: MuRata; TaMin_C: -55°C; Polarized: N; SizeAreaWB_mm2: 6.75; U/M: EA; Value: 1uF; TaMax_C: 125°C; SizeZ_mm: 1.45; SizeX_mm: 2; SizeY_mm: 1.25; Cap_Case: 0805; SizeArea_mm2: 2.5; AEC Qualified: Y; AEC Grade: 1; AEC Category: Q200
C4 = CMP-0079153-1: CAP, CERM, 10 µF, 10 V,+/- 10%, X7R, AEC-Q200 Grade 1, 0805; Manufacturer: MuRata; SizeAreaWB_mm2: 6.75; SizeArea_mm2: 2.5; AEC Qualified: Y; AEC Category: Q200; Value: 10uF; TaMax_C: 125°C; SizeZ_mm: 1.45; AEC Grade: 1; Polarized: N; TaMin_C: -55°C; SizeY_mm: 1.25; U/M: EA; SizeX_mm: 2; Cap_Case: 0805
C5 = CMP-0007147-5: CAP, CERM, 0.015 uF, 100 V, +/- 10%, X7R, AEC-Q200 Grade 1, 0603; Manufacturer: MuRata; TaMin_C: -55°C; Polarized: N; SizeAreaWB_mm2: 4.68; Value1: Unknown; U/M: EA; TaMax_C: 125°C; SizeZ_mm: 1; SizeX_mm: 1.6; SizeY_mm: 0.8; Cap_Case: 0603; SizeArea_mm2: 1.28; AEC Qualified: Y; AEC Category: Q200
C6 = CMP-0007064-4: CAP, CERM, 500 pF, 50 V, +/- 5%, C0G/NP0, 0603; Manufacturer: Yageo America; TaMin_C: -55°C; Polarized: N; SizeAreaWB_mm2: 4.68; Value1: Unknown; U/M: EA; Value: 500pF; TaMax_C: 125°C; SizeZ_mm: 1; SizeX_mm: 1.6; SizeY_mm: 0.8; Cap_Case: 0603; SizeArea_mm2: 1.28; AEC Category: Q200
C7 = CMP-0006988-4: CAP, CERM, 10 pF, 50 V, +/- 5%, C0G/NP0, 0603; Manufacturer: TDK; TaMin_C: -55°C; ESR_ohm: 0.3492; Polarized: N; SizeAreaWB_mm2: 4.68; Value1: 0.3492 ohm; U/M: EA; Value: 10pF; TaMax_C: 125°C; SizeZ_mm: 1; SizeX_mm: 1.6; SizeY_mm: 0.8; Cap_Case: 0603; SizeArea_mm2: 1.28; AEC Category: Q200
C8 = CMP-0006925-5: CAP, CERM, 0.33 uF, 10 V, +/- 10%, X5R, 0603; Manufacturer: Kemet; TaMin_C: -55°C; Polarized: N; SizeAreaWB_mm2: 4.68; Value1: Unknown; U/M: EA; Value: 0.33uF; TaMax_C: 85°C; SizeZ_mm: 1; SizeX_mm: 1.6; SizeY_mm: 0.8; Cap_Case: 0603; Value2: 10V; SizeArea_mm2: 1.28; Cap_F: 330nF; AEC Category: Q200
C9 C10 = CMP-0006960-4: CAP, CERM, 680 pF, 50 V, +/- 10%, X7R, 0603; Manufacturer: Kemet; TaMin_C: -55°C; Polarized: N; SizeAreaWB_mm2: 4.68; Value1: Unknown; U/M: EA; TaMax_C: 125°C; SizeZ_mm: 1; SizeX_mm: 1.6; SizeY_mm: 0.8; Cap_Case: 0603; Value2: 50V; SizeArea_mm2: 1.28; AEC Category: Q200
C11 C12 = CMP-0085815-1: CAP, CERM, 68 pF, 50 V,+/- 1%, C0G/NP0, 0402; Manufacturer: AVX; SizeArea_mm2: 0.5; SizeAreaWB_mm2: 3; Green_REACh: Incomplete; TaMax_C: 125°C; Value: 68pF; Cap_Case: 0402; SizeX_mm: 1; TaMin_C: -55°C; AEC Qualified: N; AEC Category: Q200; SizeZ_mm: 0.6; U/M: EA; Green_Lifecycle: Active
C16 = CMP-0007868-2: CAP, CERM, 3.3 uF, 25 V, +/- 10%, X7R, 0805; Manufacturer: TDK; TaMin_C: -55°C; Polarized: N; SizeAreaWB_mm2: 6.75; Value1: Unknown; U/M: EA; Value: 3.3uF; TaMax_C: 125°C; SizeZ_mm: 1.45; SizeX_mm: 2; SizeY_mm: 1.25; Cap_Case: 0805; SizeArea_mm2: 2.5; AEC Category: Q200
C17 = CMP-0006989-4: CAP, CERM, 100 pF, 50 V, +/- 5%, C0G/NP0, 0603; Manufacturer: TDK; TaMin_C: -55°C; Polarized: N; SizeAreaWB_mm2: 4.68; Value1: Unknown; U/M: EA; Value: 100pF; TaMax_C: 125°C; SizeZ_mm: 1; SizeX_mm: 1.6; SizeY_mm: 0.8; Cap_Case: 0603; SizeArea_mm2: 1.28; AEC Category: Q200
C18 C19 = CMP-0007049-4: CAP, CERM, 0.047 uF, 50 V, +/- 10%, X7R, 0603; Manufacturer: TDK; TaMin_C: -55°C; ESR_ohm: 49.007m; Polarized: N; SizeAreaWB_mm2: 4.68; Value1: 0.049007 ohm; U/M: EA; TaMax_C: 125°C; SizeZ_mm: 1; SizeX_mm: 1.6; SizeY_mm: 0.8; Cap_Case: 0603; SizeArea_mm2: 1.28; IRMS_A: 767.528mA; AEC Category: Q200
C20 = CMP-0007969-2: CAP, CERM, 0.1 uF, 100 V, +/- 10%, X7R, AEC-Q200 Grade 1, 0805; Manufacturer: TDK; TaMin_C: -55°C; ESR_ohm: 20.726m; Polarized: N; SizeAreaWB_mm2: 6.75; Value1: 0.020726 ohm; U/M: EA; Value: 0.1uF; TaMax_C: 125°C; SizeZ_mm: 1.45; SizeX_mm: 2; SizeY_mm: 1.25; Cap_Case: 0805; SizeArea_mm2: 2.5; AEC Qualified: Y; IRMS_A: 1.456A; AEC Grade: 1; AEC Category: Q200
C21-C24 C31-C40 = CMP-0087970-1: 10µF ±10% 100V Ceramic Capacitor X7S 1210 (3225 Metric); Manufacturer: Murata; Symbol Name: SYM-GRM32EC72A106KE05L; AEC Qualified: No; TempCo: 22%; SizeZ_mm: 2.7mm
C25-C28 = CMP-0120360-1: Aluminum Hybrid Polymer Capacitors 220uF 20% 50V Life 4000Hours AEC-Q200 RADIAL SMT; Manufacturer: Panasonic; AEC Grade: Grade 1; AEC Qualified: Yes; Cap_F: 220µF; IRMS_A: 5.2A; SizeZ_mm: 16.8mm; Dissipation Factor: 10%; Esr: 10mΩ; Leakage Current: 110uA; Value: 220µF
C61-C68 = CMP-0120392-1: Aluminum Hybrid Polymer Capacitors 150uF 20% 63V Life 4000Hours AEC-Q200 RADIAL SMT; Manufacturer: Panasonic; AEC Grade: Grade 1; AEC Qualified: Yes; Cap_F: 150µF; IRMS_A: 5.2A; SizeZ_mm: 16.8mm; Dissipation Factor: 8%; Esr: 10mΩ; Leakage Current: 94.5uA; Value: 150µF
D1-D4 = CMP-0028832-2: Diode, Schottky, 100 V, 12 A, AEC-Q101, TO-277A; Manufacturer: Vishay-Semiconductor; SizeArea_mm2: 30.875; Vf_V: 700mV; TJmax_C: 150°C; SizeZ_mm: 1.2; AEC Category: Q101; Value2: 0.7V; Green_Lifecycle: Not Set; SizeY_mm: 4.75; Green_REACh: Incomplete; Value1: 12A; SizeX_mm: 6.5; AEC Qualified: Y; SizeAreaWB_mm2: 57.375
J1-J4 = CMP-0055387-2: Standard Banana Jack, Uninsulated, 15A; Manufacturer: Cinch Connectivity; CNHeader: FALSE; Green_Lifecycle: Active; Green_REACh: Passed; CT: TRUE
J5-J8 J11 J12 JP4-JP6 = CMP-0054794-2: Header, 2.54 mm, 2x1, Gold, TH; Manufacturer: Wurth Elektronik; Shrouded: N; Gender: Male; Green_REACh: Passed; Pitch_mm: 2.54; Green_Lifecycle: Active; Row_Count: 1; Cert_UL: Y
J9 J10 = CMP-0075423-1: Header, 100mil, 12x2, Gold, TH; Manufacturer: Samtec; Pitch_mm: 2.54; Cert_VDE: N; Gender: Male; Cert_CSA: Y; Current_A: 6.3A; Voltage_V: 550V; CT: False; Row_Count: 2; CNHeader: True
J13 = CMP-0055448-2: Header (shrouded), 100mil, 5x2, High-Temperature, Gold, TH; PartNumber: N2510-6002-RB; Manufacturer: 3M; Green_Lifecycle: Active; Green_REACh: Passed
J14 = CMP-0054792-1: Header, 2.54 mm, 1x1, Gold, TH; Manufacturer: Wurth Elektronik; CNHeader: TRUE; CT: FALSE
JP1-JP3 = CMP-0054796-4: Header, 2.54 mm, 3x1, Gold, TH; Manufacturer: Wurth Elektronik; Green_Lifecycle: Active; Green_REACh: Passed; CT: FALSE; CNHeader: TRUE
L1 L2 = CMP-0750174-1: Inductor, Shielded, 3.3 µH, 32.2 A, 0.00327 ohm, AEC-Q200 Grade 0, SMD; Manufacturer: Vishay-Dale; Value: 3.3uH; AEC Grade: 0; SizeAreaWB_mm2: 366.7225; AEC Category: Q200; AEC Qualified: Y; Irms: 32.2A @ 40C rise; SizeX_mm: 17.15; Value2: 32.2A; SizeZ_mm: 7; Isat: 32A @ 20% inductance drop; SizeArea_mm2: 294.1225; DCR_ohm: 3.27m
NT1 = CMP-0078142-6: Single point connection between nets.
Q1-Q8 = CMP-0000853-1: MOSFET, N-CH, 60 V, 71 A, SO-8FL; PartNumber: NTMFS5C670NLT1G; Alternate Manufacturer: None; Manufacturer: ON Semiconductor; Value2: 20 nC; QgTyp_nC: 20; VdsMax_V: 60V; Value1: 0.008; Rdson45_ohm: 8.8m; SizeAreaWB_mm2: 58.2725; AEC Category: Q101; SizeX_mm: 6.15; Vgs_V: 20V; IdsMax_A: 71A; SizeZ_mm: 1.1; SizeY_mm: 5.15; AEC Qualified: N; Value: 60V; SizeArea_mm2: 31.6725; U/M: EA
R1-R4 = CMP-0084409-1: RES, 0.0015, 5%, 2 W, 2512 WIDE; Manufacturer: Rohm; Value_Code: 1L500; Res_ohm: 1.5m; AEC Qualified: N; Value: 0.0015; SizeArea_mm2: 20.16; SizeY_mm: 6.3; SizeAreaWB_mm2: 43.16; AEC Category: Q200; Power_W: 2W; SizeX_mm: 3.2; TempCo: 100 ppm/C; SizeZ_mm: 0.7
R5 = CMP-0022204-4: RES, 20.0 k, 1%, 0.1 W, AEC-Q200 Grade 0, 0603; Manufacturer: Vishay-Dale; Power_W: 100mW; TempCo: 100 ppm/C; Value_Code: 20k0; Value: 20.0k; EIA_Code: E96; Res_ohm: 20k; SizeX_mm: 1.6; SizeY_mm: 0.8; SizeZ_mm: 1; Value2: 0.1W; SizeArea_mm2: 1.28; AEC Qualified: Y; VDC_V: 75V; AEC Category: Q200; AEC Grade: 0
R6 = CMP-0024471-3: RES, 78.7 k, 0.1%, 0.1 W, 0603; Manufacturer: Yageo America; Power_W: 100mW; TempCo: 25 ppm/C; Value_Code: 78k7; U/M: EA; Value: 78.7k; EIA_Code: E192; SizeX_mm: 1.6; SizeY_mm: 0.8; SizeZ_mm: 1; Value2: 0.1W; SizeArea_mm2: 1.28; VDC_V: 75V; AEC Category: Q200
R7 = CMP-0024266-3: RES, 47.5 k, 0.1%, 0.1 W, 0603; Manufacturer: Yageo America; Power_W: 100mW; TempCo: 25 ppm/C; Value_Code: 47k5; U/M: EA; Value: 47.5k; EIA_Code: E192; SizeX_mm: 1.6; SizeY_mm: 0.8; SizeZ_mm: 1; Value2: 0.1W; SizeArea_mm2: 1.28; VDC_V: 75V; AEC Category: Q200
R8 = CMP-0022558-4: RES, 6.04 k, 1%, 0.1 W, AEC-Q200 Grade 0, 0603; Manufacturer: Vishay-Dale; Power_W: 100mW; TempCo: 100 ppm/C; Value_Code: 6k04; Value: 6.04k; EIA_Code: E96; SizeX_mm: 1.6; SizeY_mm: 0.8; SizeZ_mm: 1; Value2: 0.1W; SizeArea_mm2: 1.28; AEC Qualified: Y; VDC_V: 75V; AEC Category: Q200; AEC Grade: 0
R9 R94 = CMP-0021424-3: RES, 75.0 k, 1%, 0.125 W, AEC-Q200 Grade 0, 0805; Manufacturer: Vishay-Dale; Power_W: 125mW; TempCo: 100 ppm/C; Value_Code: 75k0; Value: 75.0k; EIA_Code: E96; Res_ohm: 75k; SizeX_mm: 2; SizeY_mm: 1.25; SizeZ_mm: 1.45; Value2: 0.125W; SizeArea_mm2: 2.5; AEC Qualified: Y; VDC_V: 150V; AEC Category: Q200; AEC Grade: 0
R10 = CMP-0020536-3: RES, 39 k, 5%, 0.125 W, AEC-Q200 Grade 0, 0805; Manufacturer: Vishay-Dale; Power_W: 125mW; TempCo: 200 ppm/C; Value_Code: 39k0; Value: 39k; EIA_Code: E24; SizeX_mm: 2; SizeY_mm: 1.25; SizeZ_mm: 1.45; Value2: 0.125W; SizeArea_mm2: 2.5; AEC Qualified: Y; VDC_V: 150V; AEC Category: Q200; AEC Grade: 0
R11-R14 = CMP-0122265-1: 0 Ohms Jumper Chip Resistor 0805 (2012 Metric) Metal Element; Manufacturer: Vishay; AEC Qualified: No; Power_W: 125mW; SizeZ_mm: 0.457mm; TempCo: 3900ppm/°C
R15-R18 R39-R41 R57 R73 = CMP-0023343-3: RES, 0, 1%, 0.1 W, AEC-Q200 Grade 0, 0603; Manufacturer: Stackpole Electronics Inc; Power_W: 100mW; TempCo: ppm/C; U/M: EA; Value: 0; SizeX_mm: 1.6; SizeY_mm: 0.8; SizeZ_mm: 1; Value2: 0.1W; SizeArea_mm2: 1.28; AEC Qualified: Y; AEC Category: Q200
R19 = CMP-0021990-4: RES, 100 k, 1%, 0.1 W, AEC-Q200 Grade 0, 0603; Manufacturer: Vishay-Dale; Power_W: 100mW; TempCo: 100 ppm/C; Value: 100k; EIA_Code: E96; SizeX_mm: 1.6; SizeY_mm: 0.8; SizeZ_mm: 1; Value2: 0.1W; SizeArea_mm2: 1.28; AEC Qualified: Y; VDC_V: 75V; AEC Category: Q200; AEC Grade: 0
R20 R22 R24 R26 R28 = CMP-0022003-4: RES, 10.0, 1%, 0.1 W, AEC-Q200 Grade 0, 0603; Manufacturer: Vishay-Dale; Power_W: 100mW; TempCo: 100 ppm/C; Value_Code: 10R0; Value: 10.0; EIA_Code: E96; Res_ohm: 10; SizeX_mm: 1.6; SizeY_mm: 0.8; SizeZ_mm: 1; Value2: 0.1W; SizeArea_mm2: 1.28; AEC Qualified: Y; VDC_V: 75V; AEC Category: Q200; AEC Grade: 0
R21 R23 R25 R27 = CMP-0022711-2: RES, 2.20, 1%, 0.1 W, 0603; Manufacturer: Panasonic; Power_W: 100mW; TempCo: 200 ppm/C; Value_Code: 2R20; Value: 2.20; Res_ohm: 2.2; SizeX_mm: 1.6; SizeY_mm: 0.8; SizeZ_mm: 1; Value2: 0.1W; SizeArea_mm2: 1.28; AEC Category: Q200; U/M: EA
R29 R30 = CMP-0016971-3: RES, 3.24, 1%, 0.25 W, AEC-Q200 Grade 0, 1206; Manufacturer: Vishay-Dale; Power_W: 250mW; TempCo: 100 ppm/C; Value_Code: 3R24; Value: 3.24; EIA_Code: E96; SizeX_mm: 3.2; SizeY_mm: 1.6; SizeZ_mm: 1.35; Value2: 0.25W; SizeArea_mm2: 5.12; AEC Qualified: Y; VDC_V: 200V; AEC Category: Q200; AEC Grade: 0
R31-R38 = CMP-0025950-3: RES, 100 k, 1%, 0.063 W, AEC-Q200 Grade 0, 0402; Manufacturer: Vishay-Dale; Power_W: 63mW; TempCo: 100 ppm/C; Value: 100k; EIA_Code: E96; SizeX_mm: 1; SizeY_mm: 0.5; SizeZ_mm: 0.6; Value2: 0.063W; AEC Qualified: Y; VDC_V: 50V; AEC Category: Q200; AEC Grade: 0
R42 R58 R74 = CMP-0022481-5: RES, 511, 1%, 0.1 W, AEC-Q200 Grade 0, 0603; Manufacturer: Vishay-Dale; Power_W: 100mW; TempCo: 100 ppm/C; Value_Code: 511R; Value: 511; EIA_Code: E96; SizeX_mm: 1.6; SizeY_mm: 0.8; SizeZ_mm: 1; Value2: 0.1W; SizeArea_mm2: 1.28; AEC Qualified: Y; VDC_V: 75V; AEC Category: Q200; AEC Grade: 0
R43 R59 R75 = CMP-0022120-4: RES, 1.30 k, 1%, 0.1 W, AEC-Q200 Grade 0, 0603; Manufacturer: Vishay-Dale; Power_W: 100mW; TempCo: 100 ppm/C; Value_Code: 1k30; Value: 1.30k; EIA_Code: E96; Res_ohm: 1.3k; SizeX_mm: 1.6; SizeY_mm: 0.8; SizeZ_mm: 1; Value2: 0.1W; SizeArea_mm2: 1.28; AEC Qualified: Y; VDC_V: 75V; AEC Category: Q200; AEC Grade: 0
R44 R60 R76 = CMP-0022135-4: RES, 1.87 k, 1%, 0.1 W, AEC-Q200 Grade 0, 0603; Manufacturer: Vishay-Dale; Power_W: 100mW; TempCo: 100 ppm/C; Value_Code: 1k87; Value: 1.87k; EIA_Code: E96; SizeX_mm: 1.6; SizeY_mm: 0.8; SizeZ_mm: 1; Value2: 0.1W; SizeArea_mm2: 1.28; AEC Qualified: Y; VDC_V: 75V; AEC Category: Q200; AEC Grade: 0
R45 R61 R77 = CMP-0022281-4: RES, 2.74 k, 1%, 0.1 W, AEC-Q200 Grade 0, 0603; Manufacturer: Vishay-Dale; Power_W: 100mW; TempCo: 100 ppm/C; Value_Code: 2k74; Value: 2.74k; EIA_Code: E96; SizeX_mm: 1.6; SizeY_mm: 0.8; SizeZ_mm: 1; Value2: 0.1W; SizeArea_mm2: 1.28; AEC Qualified: Y; VDC_V: 75V; AEC Category: Q200; AEC Grade: 0
R46 R62 R78 = CMP-0022381-4: RES, 3.83 k, 1%, 0.1 W, AEC-Q200 Grade 0, 0603; Manufacturer: Vishay-Dale; Power_W: 100mW; TempCo: 100 ppm/C; Value_Code: 3k83; Value: 3.83k; EIA_Code: E96; SizeX_mm: 1.6; SizeY_mm: 0.8; SizeZ_mm: 1; Value2: 0.1W; SizeArea_mm2: 1.28; AEC Qualified: Y; VDC_V: 75V; AEC Category: Q200; AEC Grade: 0
R47 R63 R79 = CMP-0022509-4: RES, 5.11 k, 1%, 0.1 W, AEC-Q200 Grade 0, 0603; Manufacturer: Vishay-Dale; Power_W: 100mW; TempCo: 100 ppm/C; Value_Code: 5k11; Value: 5.11k; EIA_Code: E96; SizeX_mm: 1.6; SizeY_mm: 0.8; SizeZ_mm: 1; Value2: 0.1W; SizeArea_mm2: 1.28; AEC Qualified: Y; VDC_V: 75V; AEC Category: Q200; AEC Grade: 0
R48 R64 R80 = CMP-0022561-4: RES, 6.49 k, 1%, 0.1 W, AEC-Q200 Grade 0, 0603; Manufacturer: Vishay-Dale; Power_W: 100mW; TempCo: 100 ppm/C; Value_Code: 6k49; Value: 6.49k; EIA_Code: E96; SizeX_mm: 1.6; SizeY_mm: 0.8; SizeZ_mm: 1; Value2: 0.1W; SizeArea_mm2: 1.28; AEC Qualified: Y; VDC_V: 75V; AEC Category: Q200; AEC Grade: 0
R49 R65 R81 = CMP-0022635-4: RES, 8.25 k, 1%, 0.1 W, AEC-Q200 Grade 0, 0603; Manufacturer: Vishay-Dale; Power_W: 100mW; TempCo: 100 ppm/C; Value_Code: 8k25; Value: 8.25k; EIA_Code: E96; SizeX_mm: 1.6; SizeY_mm: 0.8; SizeZ_mm: 1; Value2: 0.1W; SizeArea_mm2: 1.28; AEC Qualified: Y; VDC_V: 75V; AEC Category: Q200; AEC Grade: 0
R50 R66 R82 = CMP-0022000-4: RES, 10.5 k, 1%, 0.1 W, AEC-Q200 Grade 0, 0603; Manufacturer: Vishay-Dale; Power_W: 100mW; TempCo: 100 ppm/C; Value_Code: 10k5; Value: 10.5k; EIA_Code: E96; SizeX_mm: 1.6; SizeY_mm: 0.8; SizeZ_mm: 1; Value2: 0.1W; SizeArea_mm2: 1.28; AEC Qualified: Y; VDC_V: 75V; AEC Category: Q200; AEC Grade: 0
R51 R67 R83 = CMP-0022043-4: RES, 13.3 k, 1%, 0.1 W, AEC-Q200 Grade 0, 0603; Manufacturer: Vishay-Dale; Power_W: 100mW; TempCo: 100 ppm/C; Value_Code: 13k3; Value: 13.3k; EIA_Code: E96; SizeX_mm: 1.6; SizeY_mm: 0.8; SizeZ_mm: 1; Value2: 0.1W; SizeArea_mm2: 1.28; AEC Qualified: Y; VDC_V: 75V; AEC Category: Q200; AEC Grade: 0
R52 R68 R84 = CMP-0022079-4: RES, 16.2 k, 1%, 0.1 W, AEC-Q200 Grade 0, 0603; Manufacturer: Vishay-Dale; Power_W: 100mW; TempCo: 100 ppm/C; Value_Code: 16k2; Value: 16.2k; EIA_Code: E96; SizeX_mm: 1.6; SizeY_mm: 0.8; SizeZ_mm: 1; Value2: 0.1W; SizeArea_mm2: 1.28; AEC Qualified: Y; VDC_V: 75V; AEC Category: Q200; AEC Grade: 0
R53 R69 R85 = CMP-0022205-4: RES, 20.5 k, 1%, 0.1 W, AEC-Q200 Grade 0, 0603; Manufacturer: Vishay-Dale; Power_W: 100mW; TempCo: 100 ppm/C; Value_Code: 20k5; Value: 20.5k; EIA_Code: E96; SizeX_mm: 1.6; SizeY_mm: 0.8; SizeZ_mm: 1; Value2: 0.1W; SizeArea_mm2: 1.28; AEC Qualified: Y; VDC_V: 75V; AEC Category: Q200; AEC Grade: 0
R54 R70 R86 = CMP-0022237-4: RES, 24.9 k, 1%, 0.1 W, AEC-Q200 Grade 0, 0603; Manufacturer: Vishay-Dale; Power_W: 100mW; TempCo: 100 ppm/C; Value_Code: 24k9; Value: 24.9k; EIA_Code: E96; SizeX_mm: 1.6; SizeY_mm: 0.8; SizeZ_mm: 1; Value2: 0.1W; SizeArea_mm2: 1.28; AEC Qualified: Y; VDC_V: 75V; AEC Category: Q200; AEC Grade: 0
R55 R71 R87 = CMP-0022324-4: RES, 30.1 k, 1%, 0.1 W, AEC-Q200 Grade 0, 0603; Manufacturer: Vishay-Dale; Power_W: 100mW; TempCo: 100 ppm/C; Value_Code: 30k1; Value: 30.1k; EIA_Code: E96; SizeX_mm: 1.6; SizeY_mm: 0.8; SizeZ_mm: 1; Value2: 0.1W; SizeArea_mm2: 1.28; AEC Qualified: Y; VDC_V: 75V; AEC Category: Q200; AEC Grade: 0
R56 R72 R88 = CMP-0022356-4: RES, 36.5 k, 1%, 0.1 W, AEC-Q200 Grade 0, 0603; Manufacturer: Vishay-Dale; Power_W: 100mW; TempCo: 100 ppm/C; Value_Code: 36k5; Value: 36.5k; EIA_Code: E96; SizeX_mm: 1.6; SizeY_mm: 0.8; SizeZ_mm: 1; Value2: 0.1W; SizeArea_mm2: 1.28; AEC Qualified: Y; VDC_V: 75V; AEC Category: Q200; AEC Grade: 0
R89 R90 R103 R104 = CMP-0022458-4: RES, 4.99 k, 1%, 0.1 W, AEC-Q200 Grade 0, 0603; Manufacturer: Vishay-Dale; Power_W: 100mW; TempCo: 100 ppm/C; Value_Code: 4k99; Value: 4.99k; EIA_Code: E96; SizeX_mm: 1.6; SizeY_mm: 0.8; SizeZ_mm: 1; Value2: 0.1W; SizeArea_mm2: 1.28; AEC Qualified: Y; VDC_V: 75V; AEC Category: Q200; AEC Grade: 0
R91 R92 R96-R100 R105 R106 = CMP-0020442-3: RES, 0, 5%, 0.125 W, AEC-Q200 Grade 0, 0805; Manufacturer: Vishay-Dale; Power_W: 125mW; TempCo: 200 ppm/C; Value_Code: 0000; Value: 0; EIA_Code: E24; SizeX_mm: 2; SizeY_mm: 1.25; SizeZ_mm: 1.45; Value2: 0.125W; SizeArea_mm2: 2.5; AEC Qualified: Y; VDC_V: 150V; AEC Category: Q200
R93 = CMP-0021246-3: RES, 40.2 k, 1%, 0.125 W, AEC-Q200 Grade 0, 0805; Manufacturer: Vishay-Dale; Power_W: 125mW; TempCo: 100 ppm/C; Value_Code: 40k2; Value: 40.2k; EIA_Code: E96; SizeX_mm: 2; SizeY_mm: 1.25; SizeZ_mm: 1.45; Value2: 0.125W; SizeArea_mm2: 2.5; AEC Qualified: Y; VDC_V: 150V; AEC Category: Q200; AEC Grade: 0
R95 = CMP-0025874-4: RES, 0, 5%, 0.1 W, AEC-Q200 Grade 0, 0603; Manufacturer: Panasonic; Power_W: 100mW; TempCo: 600 ppm/C; Value_Code: 0000; Value: 0; EIA_Code: E24; SizeX_mm: 1.6; SizeY_mm: 0.8; SizeZ_mm: 1; Value2: 0.1W; SizeArea_mm2: 1.28; AEC Qualified: Y; VDC_V: 50V; AEC Category: Q200; SizeAreaWB_mm2: 4.68
R101 R102 = CMP-0020842-3: RES, 10.0 k, 1%, 0.125 W, AEC-Q200 Grade 0, 0805; Manufacturer: Vishay-Dale; Power_W: 125mW; TempCo: 100 ppm/C; Value_Code: 10k0; Value: 10.0k; EIA_Code: E96; Res_ohm: 10k; SizeX_mm: 2; SizeY_mm: 1.25; SizeZ_mm: 1.45; Value2: 0.125W; SizeArea_mm2: 2.5; AEC Qualified: Y; VDC_V: 150V; AEC Category: Q200; AEC Grade: 0
S1-S6 = CMP-0002229-1: Switch, SPST, 8 Pos, 25mA, 24VDC, SMD; Manufacturer: CTS Electrocomponents; CurrentRating_mA: 25A; PositionCount: 8; VDC_V: 24V; SwitchFunction: Off-On
SH-JP1-SH-JP6 = CMP-0003642-1: Shunt, 100mil, Flash Gold, Black; Manufacturer: Sullins Connector Solutions; Value: 1x2; Note: You can "mate" this to a header by matching the designator.  i.e. use SH-J3 for header J3
T1-T4 = CMP-0075010-2: Terminal 70A Lug; Manufacturer: Panduit; CompType: Screw Terminal; CT: False; Green_Lifecycle: Not Set; Green_REACh: Incomplete
TP1-TP4 = CMP-0067620-1: PC Test Point, SMT; Manufacturer: TE Connectivity
TP5 = CMP-0055143-2: Test Point, Compact, Black, TH; Manufacturer: Keystone Electronics; ContactFinish: Silver; Green_Lifecycle: Active; Green_REACh: Passed; CT: TRUE; CNHeader: FALSE
U1 = CMP-0125346-2: Wide-VIN, Dual-Phase, Automotive, Boost Controller With VOUT Tracking; Manufacturer: Texas Instruments; SizeZ_mm: 1mm; AEC Qualified: Yes; AEC Grade: Grade 1; Max Duty Cycle: 99.5%; Max Supply Voltage: 42V; Min Supply Voltage: 2.5V; Number Of Outputs: 1; Output Type: AdjustableProgrammable; Output Voltage: 6-60V; Standoff Height: 0mm; Switching Frequency: 100-2200kHz; TaMax_C: +125°C; TaMin_C: -40°C; TJmax_C: +150°C; AEC Category: Q200; CompType: IC

## Sheet SR164B_Hardware.SchDoc: Hardware
size 431 x 279 mm; Date: Not shown in title block; ApprovedBy: Not shown in title block; CheckedBy: Not shown in title block; Author: Not shown in title block; CompanyName: Not shown in title block; Engineer: Not shown in title block; Organization: Not shown in title block; Address1: Not shown in title block; Address2: Not shown in title block; Address3: Not shown in title block; Address4: Not shown in title block; DocumentNumber: 3; Revision: Use project parameter SCH_Rev; SheetNumber: 2; SheetTotal: 2; PageSetup: Record=PageOptions¦CenterHorizontal=True¦CenterVertical=True¦PrintScale=1.00¦XCorrection=1.00¦YCorrection=1.00¦PrintKind=0¦BorderSize=5000000¦LeftOffset=0¦BottomOffset=0¦Orientation=2¦PaperLength=1000¦PaperWidth=1000¦Scale=100¦PaperSource=15¦PrintQuality=600¦MediaType=1¦DitherType=10¦PaperKind=Letter¦PrintScaleMode=1
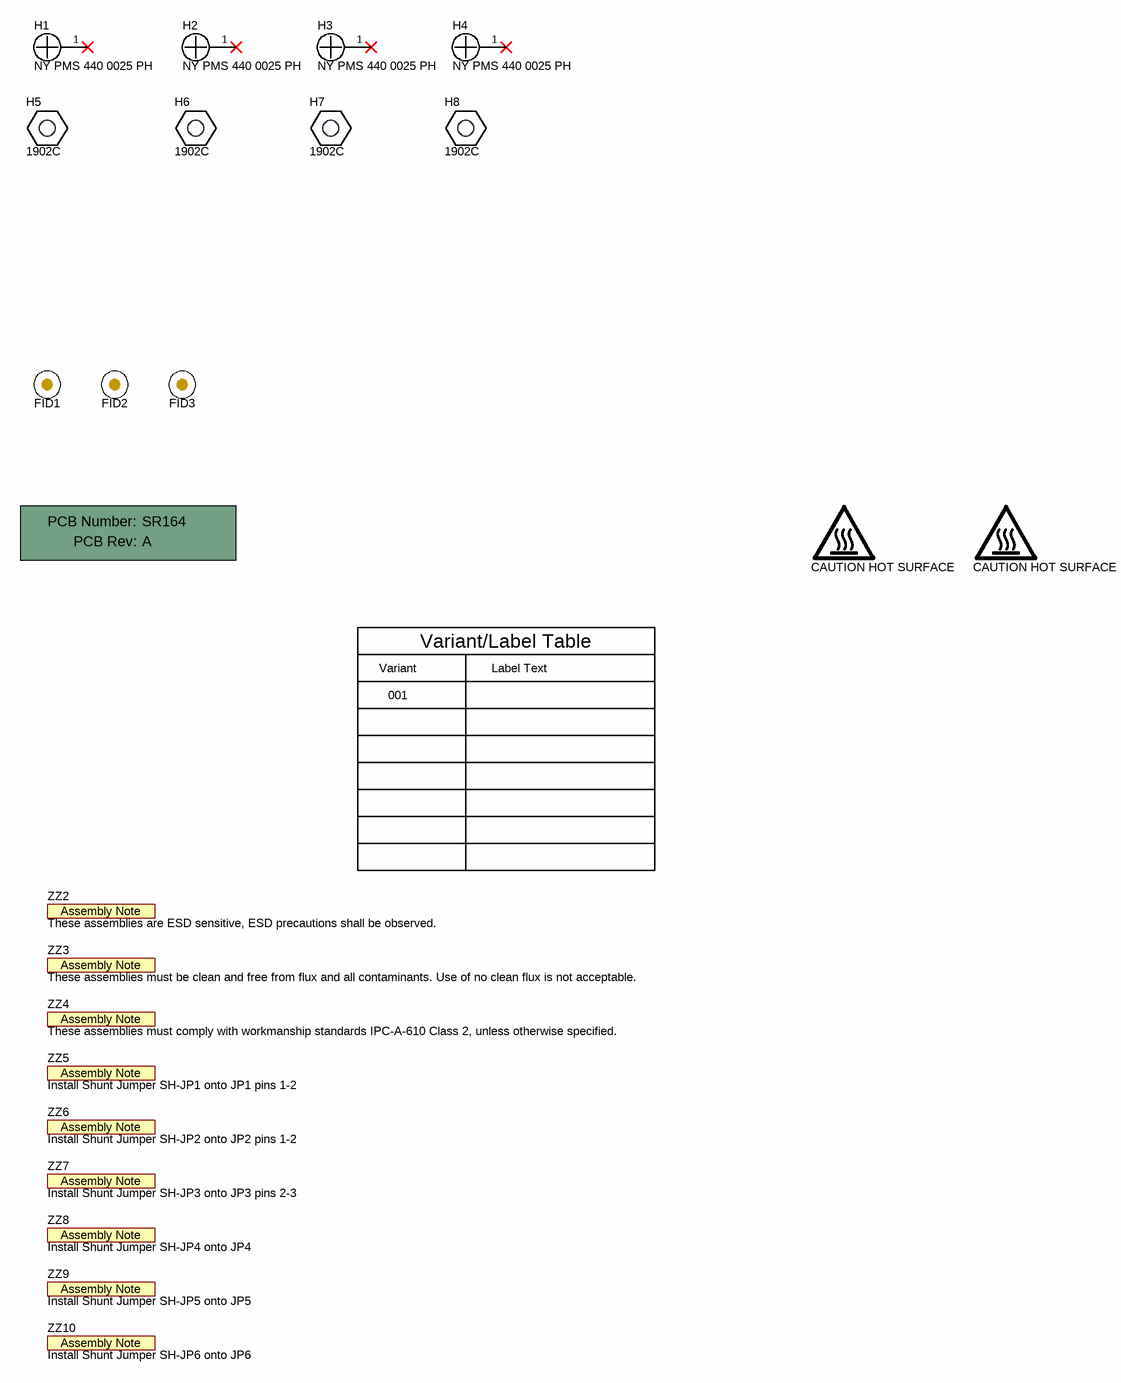
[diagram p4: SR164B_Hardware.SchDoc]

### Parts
!PCB  Printed Circuit Board  (value not drawn)  (mechanical)
FID1  Fiducial  [Fiducial10-20]  (value not drawn)
FID2  Fiducial  [Fiducial10-20]  (value not drawn)
FID3  Fiducial  [Fiducial10-20]  (value not drawn)
H1  NY PMS 440 0025 PH  [NY PMS 440 0025 PH]
H2  NY PMS 440 0025 PH  [NY PMS 440 0025 PH]
H3  NY PMS 440 0025 PH  [NY PMS 440 0025 PH]
H4  NY PMS 440 0025 PH  [NY PMS 440 0025 PH]
H5  1902C  [Keystone_1902C]
H6  1902C  [Keystone_1902C]
H7  1902C  [Keystone_1902C]
H8  1902C  [Keystone_1902C]
Logo5  CAUTION HOT SURFACE  [IEC_HotSurface_Small]  (no BOM)
Logo6  CAUTION HOT SURFACE  [IEC_HotSurface_Small]  (no BOM)
ZZ2  These assemblies are ESD sensitive, ESD precautions shall be observed.  [AssemblyNote]  (no BOM)
ZZ3  These assemblies must be clean and free from flux and all contaminants. Use of no clean flux is not acceptable.  [AssemblyNote]  (no BOM)
ZZ4  These assemblies must comply with workmanship standards IPC-A-610 Class 2, unless otherwise specified.  [AssemblyNote]  (no BOM)
ZZ5  Install Shunt Jumper SH-JP1 onto JP1 pins 1-2  [AssemblyNote]  (no BOM)
ZZ6  Install Shunt Jumper SH-JP2 onto JP2 pins 1-2  [AssemblyNote]  (no BOM)
ZZ7  Install Shunt Jumper SH-JP3 onto JP3 pins 2-3  [AssemblyNote]  (no BOM)
ZZ8  Install Shunt Jumper SH-JP4 onto JP4  [AssemblyNote]  (no BOM)
ZZ9  Install Shunt Jumper SH-JP5 onto JP5  [AssemblyNote]  (no BOM)
ZZ10  Install Shunt Jumper SH-JP6 onto JP6  [AssemblyNote]  (no BOM)

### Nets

Not connected (* = marked no-connect by the designer): H1 1*; H2 1*; H3 1*; H4 1*

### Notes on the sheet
- Variant
- Variant/Label Table
- Label Text
- 001

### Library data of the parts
!PCB = CMP-0003618-2: Manufacturer: Any; PartNumber: SR164
FID1-FID3 = CMP-0077181-1: Fiducial mark.  There is nothing to buy or mount.
H1-H4 = CMP-0003617-1: Machine Screw, Round, #4-40 x 1/4, Nylon, Philips panhead; Manufacturer: B&F Fastener Supply; CompType: Hardware
H5-H8 = CMP-0003610-1: Standoff, Hex, 0.5"L #4-40 Nylon; Manufacturer: Keystone; CompType: Hardware
Logo5 Logo6 = CMP-0074837-2: IEC 61010-1 Hot Surface Warning; Manufacturer: Texas Instruments; CompType: IC; AEC Category: Q200; SymbolCreator: a0412235
ZZ2 = CMP-0077236-1
ZZ3 = CMP-0077237-1
ZZ4 = CMP-0077238-1
ZZ5-ZZ10 = CMP-0077238-1: These assemblies must comply with workmanship standards IPC-A-610 Class 2, unless otherwise specified.

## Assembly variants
001: not fitted C9 C10 C11 C12 C22 C24 C26 C28 C35 C40 C46 C47 C48 C49 C50 C56 C57 C58 C59 C60 C64 C68 D3 D4 H1 H2 H3 H4 H5 H6 H7 H8 J11 J12 J13 Q5 Q6 Q7 Q8 R3 R4 R12 R14 R25 R26 R27 R28 R29 R30 R35 R36 R37 R38 R92 R99 R101 R102 R105 R106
